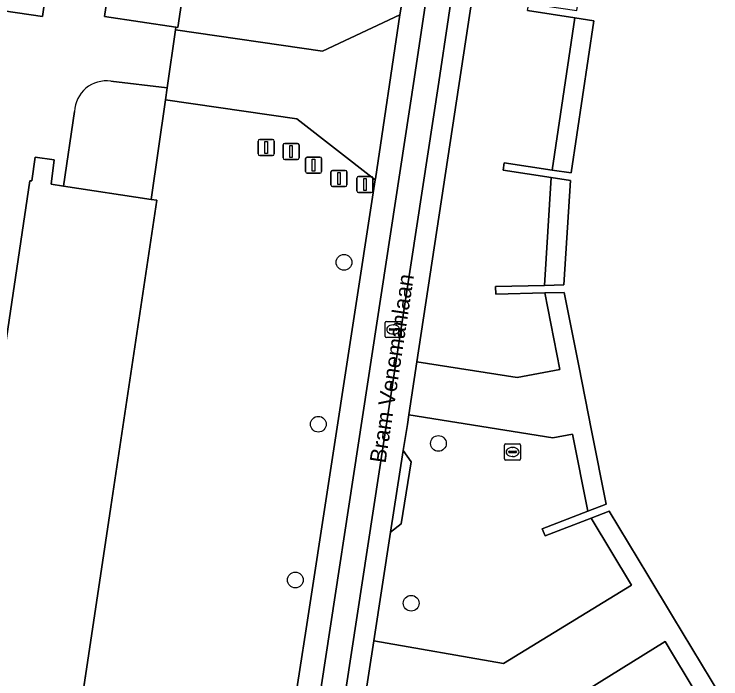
# Model space of a CAD drawing. Extents: x 161090 to 161692, y 379509 to 380907.
# Drawn here: x 161459.19 to 161503, y 380310.03 to 380351.25 of the extents above; entities that cross this region are included whole.
import ezdxf

# ---------------------------------------------------------------- set-up
doc = ezdxf.new("R2010")
doc.units = 0
for name, color, linetype in [('IMGEO_Afsluitpaal', 7, 'Continuous'), ('IMGEO_Berm_halfverhard', 7, 'Continuous'), ('IMGEO_Boom', 7, 'Continuous'), ('IMGEO_Brandkraan', 7, 'Continuous'), ('IMGEO_Groenvoorziening', 7, 'Continuous'), ('IMGEO_Hek', 7, 'Continuous'), ('IMGEO_Lichtmast', 7, 'Continuous'), ('IMGEO_Openbare_ruimte_label', 7, 'Continuous'), ('IMGEO_Pand', 7, 'Continuous'), ('IMGEO_Rijbaan_lokaal_gesloten', 7, 'Continuous'), ('IMGEO_Rijbaan_lokaal_open', 7, 'Continuous'), ('IMGEO_Rioolput', 7, 'Continuous'), ('IMGEO_Voetpad_gesloten', 7, 'Continuous'), ('IMGEO_Voetpad_open', 7, 'Continuous')]:
    doc.layers.add(name, color=color, linetype=linetype)

msp = doc.modelspace()

# ---------------------------------------------------------------- linework, layer by layer
at = {"layer": 'IMGEO_Afsluitpaal'}
for p, q in [((161474.317, 380342.579), (161474.317, 380343.379)), ((161474.317, 380343.379), (161474.317, 380342.579)), ((161474.417, 380343.479), (161475.207, 380343.479)), ((161475.207, 380343.479), (161474.417, 380343.479)), ((161475.307, 380343.379), (161475.307, 380342.579)), ((161475.307, 380342.579), (161475.307, 380343.379)), ((161475.96, 380343.236), (161476.75, 380343.236)), ((161476.75, 380343.236), (161475.96, 380343.236)), ((161475.86, 380342.336), (161475.86, 380343.136)), ((161475.86, 380343.136), (161475.86, 380342.336)), ((161476.85, 380343.136), (161476.85, 380342.336)), ((161476.85, 380342.336), (161476.85, 380343.136)), ((161475.207, 380342.479), (161474.417, 380342.479)), ((161474.417, 380342.479), (161475.207, 380342.479)), ((161477.253, 380341.489), (161477.253, 380342.289)), ((161477.253, 380342.289), (161477.253, 380341.489)), ((161477.353, 380342.389), (161478.143, 380342.389)), ((161478.143, 380342.389), (161477.353, 380342.389)), ((161478.243, 380342.289), (161478.243, 380341.489)), ((161478.243, 380341.489), (161478.243, 380342.289)), ((161476.75, 380342.236), (161475.96, 380342.236)), ((161475.96, 380342.236), (161476.75, 380342.236)), ((161478.143, 380341.389), (161477.353, 380341.389)), ((161477.353, 380341.389), (161478.143, 380341.389)), ((161478.824, 380340.663), (161478.824, 380341.463)), ((161478.824, 380341.463), (161478.824, 380340.663)), ((161478.924, 380341.563), (161479.714, 380341.563)), ((161479.714, 380341.563), (161478.924, 380341.563)), ((161479.814, 380341.463), (161479.814, 380340.663)), ((161479.814, 380340.663), (161479.814, 380341.463)), ((161479.714, 380340.563), (161478.924, 380340.563)), ((161478.924, 380340.563), (161479.714, 380340.563))]:
    msp.add_line(p, q, dxfattribs=at)
for points in [[(161474.737, 380343.354), (161474.887, 380343.354), (161474.887, 380342.604), (161474.737, 380342.604), (161474.737, 380343.354)], [(161476.28, 380343.111), (161476.43, 380343.111), (161476.43, 380342.361), (161476.28, 380342.361), (161476.28, 380343.111)], [(161477.673, 380342.264), (161477.823, 380342.264), (161477.823, 380341.514), (161477.673, 380341.514), (161477.673, 380342.264)], [(161479.244, 380341.438), (161479.394, 380341.438), (161479.394, 380340.688), (161479.244, 380340.688), (161479.244, 380341.438)]]:
    msp.add_lwpolyline(points, dxfattribs=at)
for centre, start, end in [((161474.417, 380343.379), 90, 180), ((161474.417, 380343.379), 90, 180), ((161475.207, 380343.379), 0, 90), ((161475.207, 380343.379), 360, 90), ((161475.96, 380343.136), 90, 180), ((161475.96, 380343.136), 90, 180), ((161476.75, 380343.136), 0, 90), ((161476.75, 380343.136), 360, 90), ((161474.417, 380342.579), 180, 270), ((161474.417, 380342.579), 180, 270), ((161475.207, 380342.579), 270, 0), ((161475.207, 380342.579), 270, 0), ((161475.96, 380342.336), 180, 270), ((161475.96, 380342.336), 180, 270), ((161476.75, 380342.336), 270, 0), ((161476.75, 380342.336), 270, 0), ((161477.353, 380342.289), 90, 180), ((161477.353, 380342.289), 90, 180), ((161478.143, 380342.289), 0, 90), ((161478.143, 380342.289), 360, 90), ((161477.353, 380341.489), 180, 270), ((161477.353, 380341.489), 180, 270), ((161478.143, 380341.489), 270, 0), ((161478.143, 380341.489), 270, 0), ((161478.924, 380341.463), 90, 180), ((161478.924, 380341.463), 90, 180), ((161479.714, 380341.463), 0, 90), ((161479.714, 380341.463), 360, 90), ((161478.924, 380340.663), 180, 270), ((161478.924, 380340.663), 180, 270), ((161479.714, 380340.663), 270, 0), ((161479.714, 380340.663), 270, 0)]:
    msp.add_arc(centre, 0.1, start, end, dxfattribs=at)
at = {"layer": 'IMGEO_Berm_halfverhard'}
msp.add_lwpolyline([(161493.943, 380351.023), (161491.02, 380351.468), (161491.087, 380351.92), (161494.074, 380351.47), (161494.486, 380354.17), (161490.954, 380354.723), (161491.059, 380355.474), (161488.137, 380355.942), (161484.156, 380329.687), (161490.363, 380328.707), (161493.012, 380329.207), (161492.093, 380333.96), (161489.054, 380333.883), (161489.035, 380334.359), (161492.054, 380334.428), (161492.487, 380341.117), (161489.494, 380341.575), (161489.557, 380342.03), (161492.538, 380341.579)], close=True, dxfattribs=at)
at = {"layer": 'IMGEO_Boom'}
for centre in [(161479.634, 380335.858), (161478.047, 380325.817), (161485.488, 380324.628), (161476.616, 380316.155), (161483.801, 380314.715)]:
    msp.add_circle(centre, 0.489, dxfattribs=at)
at = {"layer": 'IMGEO_Brandkraan'}
for p, q in [((161489.584, 380323.671), (161489.584, 380324.523)), ((161489.659, 380324.597), (161490.511, 380324.597)), ((161490.072, 380324.377), (161490.097, 380324.377)), ((161490.585, 380324.523), (161490.585, 380323.671)), ((161489.843, 380324.091), (161489.843, 380324.103)), ((161490.281, 380324.054), (161489.883, 380324.054)), ((161489.886, 380324.14), (161490.284, 380324.14)), ((161490.327, 380324.103), (161490.327, 380324.091)), ((161490.511, 380323.597), (161489.659, 380323.597)), ((161490.095, 380323.817), (161490.07, 380323.817))]:
    msp.add_line(p, q, dxfattribs=at)
for points in [[(161489.584, 380323.671), (161489.584, 380324.523)], [(161489.659, 380324.597), (161490.511, 380324.597)], [(161490.585, 380324.523), (161490.585, 380323.671)], [(161490.511, 380323.597), (161489.659, 380323.597)]]:
    msp.add_lwpolyline(points, dxfattribs=at)
for centre, radius, start, end in [((161489.661, 380324.521), 0.0765, 91.552, 178.448), ((161489.661, 380324.521), 0.0765, 91.552, 178.448), ((161490.509, 380324.521), 0.0765, 1.552, 88.448), ((161490.509, 380324.521), 0.0765, 1.552, 88.448), ((161489.883, 380324.1), 0.0403, 85.8775, 175.7526), ((161489.88, 380324.09), 0.0366, 178.938, 274.7102), ((161490.284, 380324.097), 0.043, 264.8664, 352.4533), ((161490.288, 380324.102), 0.0386, 1.7309, 96.639), ((161489.661, 380323.673), 0.0765, 181.552, 268.448), ((161489.661, 380323.673), 0.0765, 181.552, 268.448), ((161490.509, 380323.673), 0.0765, 271.552, 358.448), ((161490.509, 380323.673), 0.0765, 271.552, 358.448)]:
    msp.add_arc(centre, radius, start, end, dxfattribs=at)
for centre, major_axis, ratio, start_param, end_param in [((161490.071, 380324.097), (-0.387, 0.002), 0.722429, 4.712389, 7.853982), ((161490.096, 380324.097), (-0.39, 0.002), 0.717154, 1.570796, 4.712389)]:
    msp.add_ellipse(centre, major_axis=major_axis, ratio=ratio, start_param=start_param, end_param=end_param, dxfattribs=at)
at = {"layer": 'IMGEO_Groenvoorziening'}
for points in [[(161484.508, 380359.848), (161484.635, 380359.832), (161484.786, 380360.785), (161476.547, 380362.043), (161477.618, 380356.292), (161471.745, 380355.162), (161470.78, 380360.312), (161470.678, 380359.631), (161470.715, 380359.626), (161469.332, 380350.429), (161469.216, 380350.446), (161469.191, 380350.273), (161478.299, 380348.952), (161483.106, 380351.212), (161483.159, 380351.566)], [(161494.759, 380320.431), (161493.799, 380325.209), (161492.58, 380324.975), (161483.658, 380326.406), (161483.568, 380325.811), (161483.303, 380324.182), (161483.799, 380323.487), (161483.174, 380319.641), (161482.528, 380319.134), (161481.485, 380312.377), (161489.527, 380310.973), (161497.448, 380315.827), (161494.951, 380319.996), (161492.102, 380318.889), (161491.927, 380319.326)]]:
    msp.add_lwpolyline(points, close=True, dxfattribs=at)
for points in [[(161468.714, 380289.805), (161473.666, 380289.12), (161475.319, 380300.52), (161477.293, 380313.127), (161481.572, 380340.98), (161476.723, 380344.754), (161468.564, 380345.931), (161467.674, 380339.759), (161468.027, 380339.705), (161454.566, 380250), (161452.226, 380234.4), (161452.191, 380234.169), (161446.05, 380235.084), (161445.627, 380235.147), (161445.404, 380233.707), (161445.183, 380231.716), (161459.211, 380229.466), (161458.539, 380225.11), (161462.153, 380224.392)], [(161491.515, 380304.148), (161499.803, 380306.171), (161500, 380306.343), (161502.074, 380308.157), (161500, 380311.586), (161499.542, 380312.343), (161490.761, 380306.887), (161480.908, 380308.64), (161480.887, 380308.503), (161478.257, 380290.258), (161478.163, 380289.777)]]:
    msp.add_lwpolyline(points, dxfattribs=at)
at = {"layer": 'IMGEO_Hek'}
for points in [[(161468.673, 380346.684), (161469.191, 380350.273)], [(161469.191, 380350.273), (161469.216, 380350.446)], [(161468.564, 380345.931), (161468.673, 380346.684)], [(161467.674, 380339.759), (161468.564, 380345.931)]]:
    msp.add_lwpolyline(points, dxfattribs=at)
at = {"layer": 'IMGEO_Lichtmast'}
for p, q in [((161480.438, 380340.285), (161480.438, 380341.085)), ((161480.438, 380341.085), (161480.438, 380340.285)), ((161480.538, 380341.185), (161481.328, 380341.185)), ((161481.328, 380341.185), (161480.538, 380341.185)), ((161481.428, 380341.085), (161481.428, 380340.285)), ((161481.428, 380340.285), (161481.428, 380341.085)), ((161481.328, 380340.185), (161480.538, 380340.185)), ((161480.538, 380340.185), (161481.328, 380340.185))]:
    msp.add_line(p, q, dxfattribs=at)
msp.add_lwpolyline([(161480.858, 380341.06), (161481.008, 380341.06), (161481.008, 380340.31), (161480.858, 380340.31), (161480.858, 380341.06)], dxfattribs=at)
for centre, start, end in [((161480.538, 380341.085), 90, 180), ((161480.538, 380341.085), 90, 180), ((161481.328, 380341.085), 0, 90), ((161481.328, 380341.085), 360, 90), ((161480.538, 380340.285), 180, 270), ((161480.538, 380340.285), 180, 270), ((161481.328, 380340.285), 270, 0), ((161481.328, 380340.285), 270, 0)]:
    msp.add_arc(centre, 0.1, start, end, dxfattribs=at)
at = {"layer": 'IMGEO_Pand'}
msp.add_lwpolyline([(161470.715, 380359.626), (161470.678, 380359.631), (161466.151, 380360.297), (161466.132, 380360.169), (161464.796, 380351.094), (161469.216, 380350.446), (161469.332, 380350.429)], close=True, dxfattribs=at)
for points in [[(161491.02, 380351.468), (161493.943, 380351.023), (161495.129, 380350.843), (161493.724, 380341.399), (161492.538, 380341.579), (161489.557, 380342.03), (161489.494, 380341.575), (161492.487, 380341.117), (161493.673, 380340.935), (161493.254, 380334.455), (161492.054, 380334.428), (161489.035, 380334.359), (161489.054, 380333.883), (161492.093, 380333.96), (161493.293, 380333.99), (161494.191, 380329.43), (161494.977, 380325.436), (161495.877, 380320.867), (161494.759, 380320.431), (161491.927, 380319.326), (161492.102, 380318.889), (161494.951, 380319.996), (161496.069, 380320.431), (161498.471, 380316.454), (161500, 380313.923), (161502.996, 380308.963)], [(161454.566, 380250), (161468.027, 380339.705), (161467.674, 380339.759), (161462.242, 380340.585), (161461.477, 380340.701), (161461.676, 380342.209), (161460.497, 380342.387), (161460.282, 380340.917), (161460.165, 380340.92), (161458.225, 380327.954)]]:
    msp.add_lwpolyline(points, dxfattribs=at)
at = {"layer": 'IMGEO_Rijbaan_lokaal_gesloten'}
for points in [[(161466.094, 380230.202), (161483.979, 380347.225), (161485.809, 380359.378), (161485.861, 380359.57), (161495.524, 380423.042), (161498.373, 380441.757), (161497.133, 380442.017), (161496.848, 380440.038), (161494.239, 380423.359), (161493.091, 380415.845), (161489.971, 380394.788), (161489.727, 380393.141), (161486.155, 380369.726), (161485.084, 380362.709), (161484.786, 380360.785), (161484.635, 380359.832), (161484.508, 380359.848), (161483.159, 380351.566), (161483.106, 380351.212), (161481.581, 380341.038), (161481.572, 380340.98), (161477.293, 380313.127), (161475.319, 380300.52)], [(161496.967, 380422.687), (161487.325, 380359.344), (161487.307, 380359.083), (161485.505, 380347.041), (161467.599, 380229.99)], [(161480.908, 380308.64), (161481.485, 380312.377), (161482.528, 380319.134), (161483.303, 380324.182), (161483.568, 380325.811), (161483.658, 380326.406), (161484.156, 380329.687), (161488.137, 380355.942), (161488.152, 380356.038), (161488.624, 380359.109), (161488.609, 380359.226), (161488.586, 380359.396), (161488.71, 380360.213), (161489.626, 380366.224), (161490.072, 380369.148), (161492.021, 380381.94), (161493.233, 380389.891), (161493.641, 380392.567), (161494.293, 380396.846)]]:
    msp.add_lwpolyline(points, dxfattribs=at)
at = {"layer": 'IMGEO_Rijbaan_lokaal_open'}
for points in [[(161496.967, 380422.687), (161497.303, 380424.898), (161498.535, 380426.719), (161500.797, 380441.248), (161501.473, 380445.586), (161499.017, 380445.989), (161498.373, 380441.757), (161495.524, 380423.042), (161485.861, 380359.57), (161485.809, 380359.378), (161483.979, 380347.225), (161466.094, 380230.202), (161456.074, 380164.596), (161457.567, 380164.364), (161467.599, 380229.99), (161485.505, 380347.041), (161487.307, 380359.083), (161487.325, 380359.344)], [(161483.106, 380351.212), (161478.299, 380348.952), (161469.191, 380350.273), (161468.673, 380346.684), (161468.564, 380345.931), (161476.723, 380344.754), (161481.572, 380340.98), (161481.581, 380341.038)], [(161483.303, 380324.182), (161482.528, 380319.134), (161483.174, 380319.641), (161483.799, 380323.487)]]:
    msp.add_lwpolyline(points, close=True, dxfattribs=at)
at = {"layer": 'IMGEO_Rioolput'}
for p, q in [((161482.262, 380332.194), (161483.114, 380332.194)), ((161482.187, 380331.268), (161482.187, 380332.12)), ((161482.675, 380331.974), (161482.7, 380331.974)), ((161483.188, 380332.12), (161483.188, 380331.268)), ((161482.446, 380331.688), (161482.446, 380331.7)), ((161482.884, 380331.651), (161482.486, 380331.651)), ((161482.489, 380331.737), (161482.887, 380331.737)), ((161482.698, 380331.414), (161482.673, 380331.414)), ((161482.93, 380331.7), (161482.93, 380331.688)), ((161483.114, 380331.194), (161482.262, 380331.194))]:
    msp.add_line(p, q, dxfattribs=at)
for points in [[(161482.262, 380332.194), (161483.114, 380332.194)], [(161482.187, 380331.268), (161482.187, 380332.12)], [(161483.188, 380332.12), (161483.188, 380331.268)], [(161483.114, 380331.194), (161482.262, 380331.194)]]:
    msp.add_lwpolyline(points, dxfattribs=at)
for centre, radius, start, end in [((161482.264, 380332.118), 0.0765, 91.552, 178.448), ((161482.264, 380332.118), 0.0765, 91.552, 178.448), ((161483.112, 380332.118), 0.0765, 1.552, 88.448), ((161483.112, 380332.118), 0.0765, 1.552, 88.448), ((161482.486, 380331.697), 0.0403, 85.8775, 175.7526), ((161482.483, 380331.687), 0.0366, 178.938, 274.7102), ((161482.887, 380331.694), 0.043, 264.8664, 352.4533), ((161482.891, 380331.699), 0.0386, 1.7309, 96.639), ((161482.264, 380331.27), 0.0765, 181.552, 268.448), ((161482.264, 380331.27), 0.0765, 181.552, 268.448), ((161483.112, 380331.27), 0.0765, 271.552, 358.448), ((161483.112, 380331.27), 0.0765, 271.552, 358.448)]:
    msp.add_arc(centre, radius, start, end, dxfattribs=at)
for centre, major_axis, ratio, start_param, end_param in [((161482.674, 380331.694), (-0.387, 0.002), 0.722429, 4.712389, 7.853982), ((161482.699, 380331.694), (-0.39, 0.002), 0.717154, 1.570796, 4.712389)]:
    msp.add_ellipse(centre, major_axis=major_axis, ratio=ratio, start_param=start_param, end_param=end_param, dxfattribs=at)
at = {"layer": 'IMGEO_Voetpad_gesloten'}
msp.add_lwpolyline([(161450.169, 380361.331), (161450.318, 380362.308), (161437.334, 380364.233), (161436.641, 380359.607), (161436.203, 380356.676), (161449.083, 380354.725), (161448.797, 380352.894), (161460.946, 380351.094), (161461.102, 380352.136), (161449.037, 380353.924)], close=True, dxfattribs=at)
for points in [[(161465.187, 380347.087), (161468.673, 380346.684), (161469.191, 380350.273), (161469.216, 380350.446), (161464.796, 380351.094), (161466.132, 380360.169), (161462.243, 380359.399), (161461.133, 380352.131), (161461.102, 380352.136), (161460.946, 380351.094), (161448.797, 380352.894)], [(161455.54, 380310.11), (161454.284, 380310.315), (161454.711, 380313.082), (161455.966, 380312.889), (161457.79, 380325.148), (161456.541, 380325.348), (161456.943, 380328.13), (161458.225, 380327.954), (161460.165, 380340.92), (161460.282, 380340.917), (161460.497, 380342.387), (161461.676, 380342.209), (161461.477, 380340.701), (161462.242, 380340.585), (161462.936, 380345.213)]]:
    msp.add_lwpolyline(points, dxfattribs=at)
msp.add_arc((161464.889, 380345.157), 1.953, 81.2109, 178.3451, dxfattribs=at)
at = {"layer": 'IMGEO_Voetpad_open'}
for points in [[(161495.129, 380350.843), (161493.943, 380351.023), (161492.538, 380341.579), (161493.724, 380341.399)], [(161493.673, 380340.935), (161492.487, 380341.117), (161492.054, 380334.428), (161493.254, 380334.455)], [(161494.191, 380329.43), (161493.293, 380333.99), (161492.093, 380333.96), (161493.012, 380329.207), (161490.363, 380328.707), (161484.156, 380329.687), (161483.658, 380326.406), (161492.58, 380324.975), (161493.799, 380325.209), (161494.759, 380320.431), (161495.877, 380320.867), (161494.977, 380325.436)], [(161499.542, 380312.343), (161500, 380311.586), (161502.074, 380308.157), (161502.996, 380308.963), (161500, 380313.923), (161498.471, 380316.454), (161496.069, 380320.431), (161494.951, 380319.996), (161497.448, 380315.827), (161489.527, 380310.973), (161481.485, 380312.377), (161480.908, 380308.64), (161490.761, 380306.887)]]:
    msp.add_lwpolyline(points, close=True, dxfattribs=at)
msp.add_lwpolyline([(161462.936, 380345.213), (161462.242, 380340.585), (161467.674, 380339.759), (161468.564, 380345.931), (161468.673, 380346.684), (161465.187, 380347.087)], dxfattribs=at)
msp.add_arc((161464.889, 380345.157), 1.953, 81.2109, 178.3451, dxfattribs=at)

# ---------------------------------------------------------------- texts
at = {"layer": 'IMGEO_Openbare_ruimte_label'}
msp.add_text('Bram Venemanlaan', height=1, rotation=81.3758, dxfattribs=at).set_placement((161482.208, 380323.364))

doc.saveas('drawing.dxf')
